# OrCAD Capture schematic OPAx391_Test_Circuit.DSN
size A; title: OPA391 Precision, Ultra-Low IQ, Low Offset Voltage, e-trim™; rev: 1.3; note: Datasheet: SBOS925A  EVM: N/A
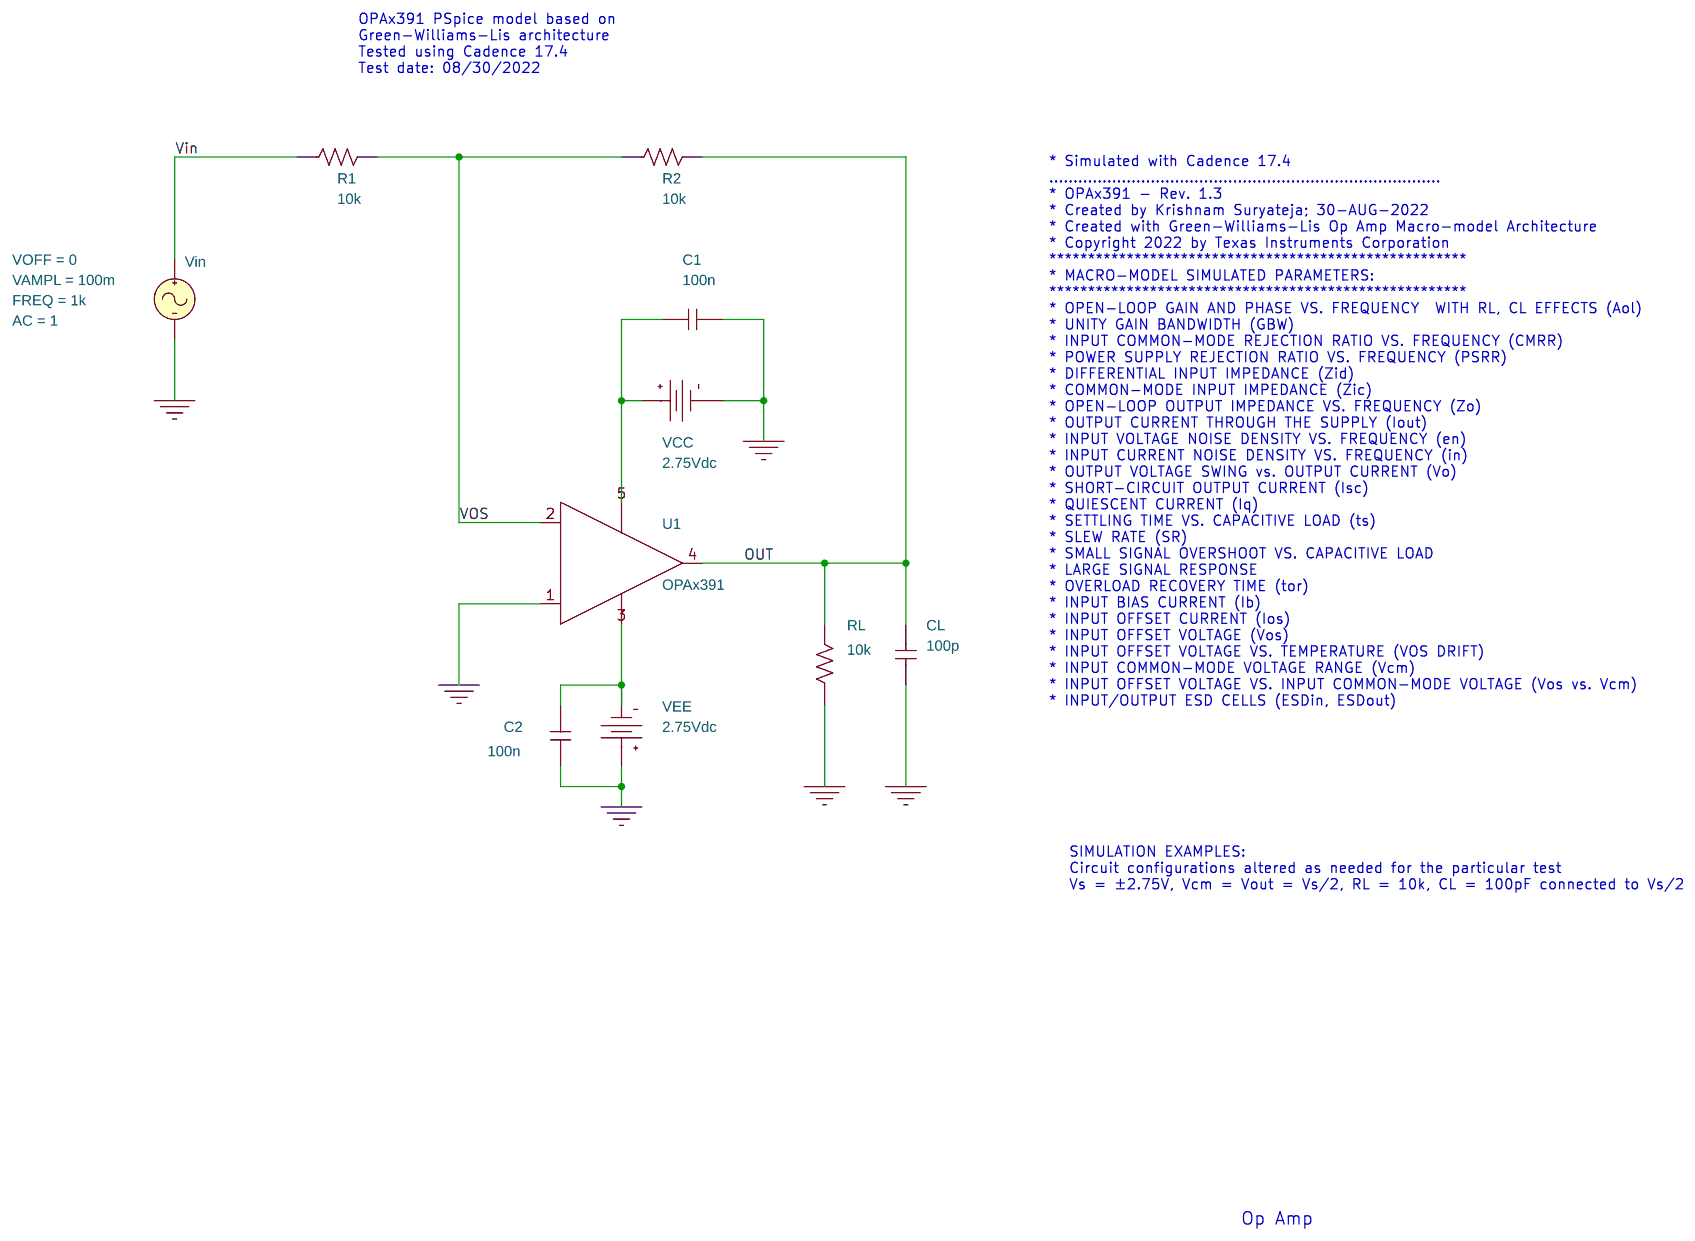
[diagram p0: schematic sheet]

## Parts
C1  100n  [cap196]
C2  100n  [cap196]
CL  100p  [RAD/CK05]
R1  10k  [AXRC05]
R2  10k  [AXRC05]
RL  10k  [AXRC05]
U1  OPAx391
VCC  VDC
VEE  VDC
Vin  VSIN

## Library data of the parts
C1 C2 CL = C
R1 R2 RL = R
U1 = OPAx391
VCC VEE = VDC: DC: 2.75Vdc
Vin = VSIN: AC: 1; FREQ: 1k; VAMPL: 100m; VOFF: 0

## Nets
Vin: R1.1 Vin.1(+)
0: C1.2 C2.1 CL.1 RL.1 U1.1(+) VCC.1(-) VEE.0(+) Vin.2(-)
OUT: CL.2 R2.2 RL.2 U1.4(OUT)
VOS: R1.2 R2.1 U1.2(-)
N27303: C1.1 U1.5(V+) VCC.0(+)
N27354: C2.2 U1.3(V-) VEE.1(-)

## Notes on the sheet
- OPAx391 PSpice model based on
  Green-Williams-Lis architecture
  Tested using Cadence 17.4
  Test date: 08/30/2022
- * Simulated with Cadence 17.4
  .................................................................................
  * OPAx391 - Rev. 1.3
  * Created by Krishnam Suryateja; 30-AUG-2022
  * Created with Green-Williams-Lis Op Amp Macro-model Architecture
  * Copyright 2022 by Texas Instruments Corporation
  ******************************************************
  * MACRO-MODEL SIMULATED PARAMETERS:
  ******************************************************
  * OPEN-LOOP GAIN AND PHASE VS. FREQUENCY  WITH RL, CL EFFECTS (Aol)
  * UNITY GAIN BANDWIDTH (GBW)
  * INPUT COMMON-MODE REJECTION RATIO VS. FREQUENCY (CMRR)
  * POWER SUPPLY REJECTION RATIO VS. FREQUENCY (PSRR)
  * DIFFERENTIAL INPUT IMPEDANCE (Zid)
  * COMMON-MODE INPUT IMPEDANCE (Zic)
  * OPEN-LOOP OUTPUT IMPEDANCE VS. FREQUENCY (Zo)
  * OUTPUT CURRENT THROUGH THE SUPPLY (Iout)
  * INPUT VOLTAGE NOISE DENSITY VS. FREQUENCY (en)
  * INPUT CURRENT NOISE DENSITY VS. FREQUENCY (in)
  * OUTPUT VOLTAGE SWING vs. OUTPUT CURRENT (Vo)
  * SHORT-CIRCUIT OUTPUT CURRENT (Isc)
  * QUIESCENT CURRENT (Iq)
  * SETTLING TIME VS. CAPACITIVE LOAD (ts)
  * SLEW RATE (SR)
  * SMALL SIGNAL OVERSHOOT VS. CAPACITIVE LOAD
  * LARGE SIGNAL RESPONSE
  * OVERLOAD RECOVERY TIME (tor)
  * INPUT BIAS CURRENT (Ib)
  * INPUT OFFSET CURRENT (Ios)
  * INPUT OFFSET VOLTAGE (Vos)
  * INPUT OFFSET VOLTAGE VS. TEMPERATURE (VOS DRIFT)
  * INPUT COMMON-MODE VOLTAGE RANGE (Vcm)
  * INPUT OFFSET VOLTAGE VS. INPUT COMMON-MODE VOLTAGE (Vos vs. Vcm)
  * INPUT/OUTPUT ESD CELLS (ESDin, ESDout)
- SIMULATION EXAMPLES:
  Circuit configurations altered as needed for the particular test
  Vs = ±2.75V, Vcm = Vout = Vs/2, RL = 10k, CL = 100pF connected to Vs/2
- Op Amp
